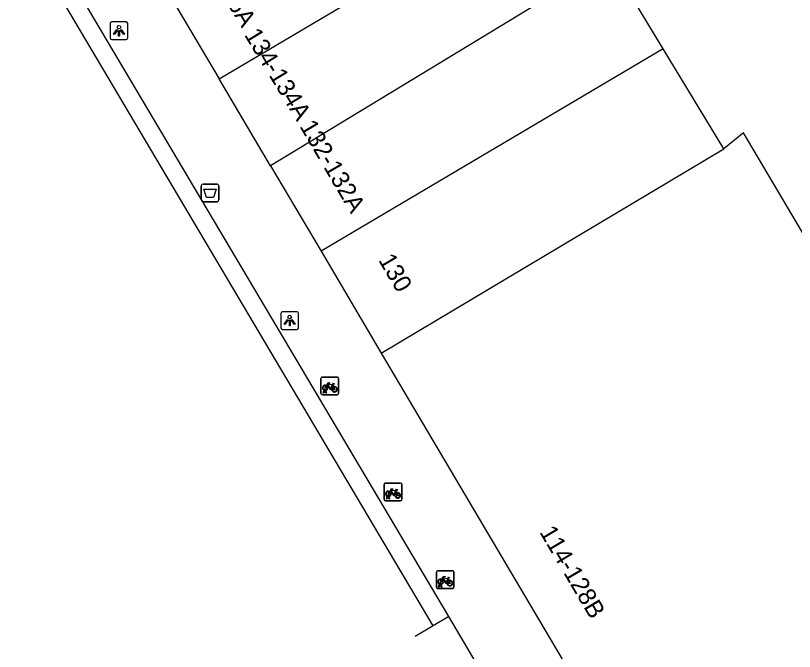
# Model space of a CAD drawing. Extents: x 160861 to 161308, y 384024 to 384878.
# Drawn here: x 161039.26 to 161083.38, y 384444.8 to 384480.81 of the extents above; entities that cross this region are included whole.
import ezdxf

# ---------------------------------------------------------------- set-up
doc = ezdxf.new("R2010")
doc.units = 0
for name, color, linetype in [('IMGEO_Afvalbak', 7, 'Continuous'), ('IMGEO_Fietsenrek', 7, 'Continuous'), ('IMGEO_Fietspad_gesloten', 7, 'Continuous'), ('IMGEO_Fietspad_open', 7, 'Continuous'), ('IMGEO_Lichtpunt', 7, 'Continuous'), ('IMGEO_Pand', 7, 'Continuous'), ('IMGEO_Pand_nummerreeks', 7, 'Continuous')]:
    doc.layers.add(name, color=color, linetype=linetype)

msp = doc.modelspace()

# ---------------------------------------------------------------- linework, layer by layer
at = {"layer": 'IMGEO_Afvalbak'}
for p, q in [((161049.779, 384470.364), (161049.779, 384471.164)), ((161049.779, 384471.164), (161049.779, 384470.364)), ((161049.879, 384471.264), (161050.669, 384471.264)), ((161050.669, 384471.264), (161049.879, 384471.264)), ((161050.769, 384471.164), (161050.769, 384470.364)), ((161050.769, 384470.364), (161050.769, 384471.164)), ((161050.669, 384470.264), (161049.879, 384470.264)), ((161049.879, 384470.264), (161050.669, 384470.264))]:
    msp.add_line(p, q, dxfattribs=at)
msp.add_lwpolyline([(161049.922, 384470.978), (161050.626, 384470.978), (161050.477, 384470.508), (161050.071, 384470.508), (161049.922, 384470.978)], dxfattribs=at)
for centre, start, end in [((161049.879, 384471.164), 90, 180), ((161049.879, 384471.164), 90, 180), ((161050.669, 384471.164), 0, 90), ((161050.669, 384471.164), 360, 90), ((161049.879, 384470.364), 180, 270), ((161049.879, 384470.364), 180, 270), ((161050.669, 384470.364), 270, 0), ((161050.669, 384470.364), 270, 0)]:
    msp.add_arc(centre, 0.1, start, end, dxfattribs=at)
at = {"layer": 'IMGEO_Fietsenrek'}
for p, q in [((161056.556, 384459.416), (161056.556, 384460.257)), ((161056.556, 384460.257), (161056.556, 384459.416)), ((161056.631, 384460.341), (161057.472, 384460.341)), ((161057.472, 384460.341), (161056.631, 384460.341)), ((161057.556, 384460.266), (161057.556, 384459.425)), ((161057.556, 384459.425), (161057.556, 384460.266)), ((161056.683, 384459.425), (161056.722, 384459.585)), ((161056.752, 384459.573), (161056.717, 384459.425)), ((161056.794, 384459.597), (161056.793, 384459.601)), ((161056.835, 384459.425), (161056.801, 384459.567)), ((161056.825, 384459.608), (161056.826, 384459.601)), ((161056.833, 384459.571), (161056.868, 384459.425)), ((161057.243, 384459.89), (161057.279, 384459.795)), ((161057.481, 384459.341), (161056.64, 384459.341)), ((161056.64, 384459.341), (161057.481, 384459.341)), ((161056.717, 384459.425), (161056.683, 384459.425)), ((161056.868, 384459.425), (161056.835, 384459.425)), ((161060.137, 384453.412), (161060.137, 384454.253)), ((161060.137, 384454.253), (161060.137, 384453.412)), ((161060.212, 384454.337), (161061.053, 384454.337)), ((161061.053, 384454.337), (161060.212, 384454.337)), ((161061.137, 384454.262), (161061.137, 384453.421)), ((161061.137, 384453.421), (161061.137, 384454.262)), ((161060.824, 384453.886), (161060.86, 384453.791)), ((161061.062, 384453.337), (161060.221, 384453.337)), ((161060.221, 384453.337), (161061.062, 384453.337)), ((161060.264, 384453.421), (161060.303, 384453.581)), ((161060.298, 384453.421), (161060.264, 384453.421)), ((161060.333, 384453.569), (161060.298, 384453.421)), ((161060.375, 384453.593), (161060.374, 384453.597)), ((161060.416, 384453.421), (161060.382, 384453.563)), ((161060.406, 384453.604), (161060.407, 384453.597)), ((161060.414, 384453.567), (161060.449, 384453.421)), ((161060.449, 384453.421), (161060.416, 384453.421)), ((161063.169, 384449.367), (161064.01, 384449.367)), ((161064.01, 384449.367), (161063.169, 384449.367)), ((161063.094, 384448.442), (161063.094, 384449.283)), ((161063.094, 384449.283), (161063.094, 384448.442)), ((161064.094, 384449.292), (161064.094, 384448.451)), ((161064.094, 384448.451), (161064.094, 384449.292)), ((161063.221, 384448.451), (161063.26, 384448.611)), ((161063.29, 384448.599), (161063.255, 384448.451)), ((161063.332, 384448.623), (161063.331, 384448.627)), ((161063.373, 384448.451), (161063.339, 384448.593)), ((161063.363, 384448.634), (161063.364, 384448.627)), ((161063.371, 384448.597), (161063.406, 384448.451)), ((161063.781, 384448.916), (161063.817, 384448.821)), ((161064.019, 384448.367), (161063.178, 384448.367)), ((161063.178, 384448.367), (161064.019, 384448.367)), ((161063.255, 384448.451), (161063.221, 384448.451)), ((161063.406, 384448.451), (161063.373, 384448.451))]:
    msp.add_line(p, q, dxfattribs=at)
for points in [[(161056.869, 384459.867), (161056.964, 384460.031), (161057.05, 384460.017), (161057.052, 384460.008), (161056.996, 384459.997), (161056.969, 384459.952), (161057.225, 384459.911)], [(161057.225, 384459.911), (161057.25, 384459.96), (161057.244, 384459.964), (161057.221, 384459.968), (161057.209, 384459.975), (161057.208, 384459.978), (161057.21, 384459.983), (161057.305, 384459.968), (161057.307, 384459.958), (161057.297, 384459.945), (161057.285, 384459.939), (161057.271, 384459.945), (161057.243, 384459.89)], [(161056.89, 384459.815), (161056.838, 384459.725), (161056.798, 384459.7), (161056.799, 384459.747), (161056.854, 384459.841)], [(161057.165, 384459.623), (161057.115, 384459.623), (161056.924, 384459.874), (161056.905, 384459.842)], [(161057.212, 384459.886), (161056.955, 384459.927), (161056.938, 384459.898), (161057.105, 384459.678), (161057.212, 384459.886)], [(161057.26, 384459.788), (161057.23, 384459.865), (161057.121, 384459.647), (161057.164, 384459.647)], [(161057.194, 384459.647), (161057.314, 384459.646), (161057.27, 384459.76)], [(161057.29, 384459.767), (161057.345, 384459.622), (161057.195, 384459.622)], [(161060.471, 384453.811), (161060.419, 384453.721), (161060.379, 384453.696), (161060.38, 384453.743), (161060.435, 384453.837)], [(161060.45, 384453.863), (161060.545, 384454.027), (161060.631, 384454.013), (161060.633, 384454.004), (161060.577, 384453.993), (161060.55, 384453.948), (161060.806, 384453.907)], [(161060.746, 384453.619), (161060.696, 384453.619), (161060.505, 384453.87), (161060.486, 384453.838)], [(161060.793, 384453.882), (161060.536, 384453.923), (161060.519, 384453.894), (161060.686, 384453.674), (161060.793, 384453.882)], [(161060.841, 384453.784), (161060.811, 384453.861), (161060.702, 384453.643), (161060.745, 384453.643)], [(161060.806, 384453.907), (161060.831, 384453.956), (161060.825, 384453.96), (161060.802, 384453.964), (161060.79, 384453.971), (161060.789, 384453.974), (161060.791, 384453.979), (161060.886, 384453.964), (161060.888, 384453.954), (161060.878, 384453.941), (161060.866, 384453.935), (161060.852, 384453.941), (161060.824, 384453.886)], [(161060.775, 384453.643), (161060.895, 384453.642), (161060.851, 384453.756)], [(161060.871, 384453.763), (161060.926, 384453.618), (161060.776, 384453.618)], [(161063.407, 384448.893), (161063.502, 384449.057), (161063.588, 384449.043), (161063.59, 384449.034), (161063.534, 384449.023), (161063.507, 384448.978), (161063.763, 384448.937)], [(161063.75, 384448.912), (161063.493, 384448.953), (161063.476, 384448.924), (161063.643, 384448.704), (161063.75, 384448.912)], [(161063.763, 384448.937), (161063.788, 384448.986), (161063.782, 384448.99), (161063.759, 384448.994), (161063.747, 384449.001), (161063.746, 384449.004), (161063.748, 384449.009), (161063.843, 384448.994), (161063.845, 384448.984), (161063.835, 384448.971), (161063.823, 384448.965), (161063.809, 384448.971), (161063.781, 384448.916)], [(161063.428, 384448.841), (161063.376, 384448.751), (161063.336, 384448.726), (161063.337, 384448.773), (161063.392, 384448.867)], [(161063.703, 384448.649), (161063.653, 384448.649), (161063.462, 384448.9), (161063.443, 384448.868)], [(161063.798, 384448.814), (161063.768, 384448.891), (161063.659, 384448.673), (161063.702, 384448.673)], [(161063.732, 384448.673), (161063.852, 384448.672), (161063.808, 384448.786)], [(161063.828, 384448.793), (161063.883, 384448.648), (161063.733, 384448.648)]]:
    msp.add_lwpolyline(points, dxfattribs=at)
for centre, radius, start, end in [((161056.634, 384460.263), 0.0779, 92.4484, 184.2845), ((161056.634, 384460.263), 0.0779, 92.4484, 184.2845), ((161057.478, 384460.263), 0.0779, 2.4484, 94.2845), ((161057.478, 384460.263), 0.0779, 2.4484, 94.2845), ((161056.796, 384459.726), 0.159, 62.6766, 242.1369), ((161056.796, 384459.726), 0.129, 63.3192, 238.903), ((161056.776, 384459.597), 0.0499, 12.8025, 158.6934), ((161056.796, 384459.726), 0.159, 253.9967, 271.7867), ((161056.776, 384459.597), 0.0174, 12.8025, 163.4502), ((161056.796, 384459.726), 0.129, 253.415, 269.0204), ((161056.796, 384459.726), 0.129, 283.6043, 43.4302), ((161056.796, 384459.726), 0.159, 283.5766, 46.6042), ((161057.323, 384459.642), 0.159, 113.3408, 178.3217), ((161057.323, 384459.642), 0.159, 187.0065, 105.7708), ((161057.323, 384459.642), 0.129, 113.923, 177.9556), ((161057.323, 384459.642), 0.129, 188.6715, 104.5883), ((161056.634, 384459.419), 0.0779, 182.4484, 274.2845), ((161056.634, 384459.419), 0.0779, 182.4484, 274.2845), ((161057.478, 384459.419), 0.0779, 272.4484, 4.2845), ((161057.478, 384459.419), 0.0779, 272.4484, 4.2845), ((161060.215, 384454.259), 0.0779, 92.4484, 184.2845), ((161060.215, 384454.259), 0.0779, 92.4484, 184.2845), ((161061.059, 384454.259), 0.0779, 2.4484, 94.2845), ((161061.059, 384454.259), 0.0779, 2.4484, 94.2845), ((161060.377, 384453.722), 0.159, 62.6766, 242.1369), ((161060.377, 384453.722), 0.129, 63.3192, 238.903), ((161060.377, 384453.722), 0.129, 283.6043, 43.4302), ((161060.377, 384453.722), 0.159, 283.5766, 46.6042), ((161060.904, 384453.638), 0.159, 113.3408, 178.3217), ((161060.904, 384453.638), 0.159, 187.0065, 105.7708), ((161060.215, 384453.415), 0.0779, 182.4484, 274.2845), ((161060.215, 384453.415), 0.0779, 182.4484, 274.2845), ((161060.357, 384453.593), 0.0499, 12.8025, 158.6934), ((161060.377, 384453.722), 0.159, 253.9967, 271.7867), ((161060.357, 384453.593), 0.0174, 12.8025, 163.4502), ((161060.377, 384453.722), 0.129, 253.415, 269.0204), ((161060.904, 384453.638), 0.129, 113.923, 177.9556), ((161060.904, 384453.638), 0.129, 188.6715, 104.5883), ((161061.059, 384453.415), 0.0779, 272.4484, 4.2845), ((161061.059, 384453.415), 0.0779, 272.4484, 4.2845), ((161063.172, 384449.289), 0.0779, 92.4484, 184.2845), ((161063.172, 384449.289), 0.0779, 92.4484, 184.2845), ((161064.016, 384449.289), 0.0779, 2.4484, 94.2845), ((161064.016, 384449.289), 0.0779, 2.4484, 94.2845), ((161063.334, 384448.752), 0.159, 62.6766, 242.1369), ((161063.334, 384448.752), 0.129, 63.3192, 238.903), ((161063.314, 384448.623), 0.0499, 12.8025, 158.6934), ((161063.334, 384448.752), 0.159, 253.9967, 271.7867), ((161063.314, 384448.623), 0.0174, 12.8025, 163.4502), ((161063.334, 384448.752), 0.129, 253.415, 269.0204), ((161063.334, 384448.752), 0.129, 283.6043, 43.4302), ((161063.334, 384448.752), 0.159, 283.5766, 46.6042), ((161063.861, 384448.668), 0.159, 113.3408, 178.3217), ((161063.861, 384448.668), 0.159, 187.0065, 105.7708), ((161063.861, 384448.668), 0.129, 113.923, 177.9556), ((161063.861, 384448.668), 0.129, 188.6715, 104.5883), ((161063.172, 384448.445), 0.0779, 182.4484, 274.2845), ((161063.172, 384448.445), 0.0779, 182.4484, 274.2845), ((161064.016, 384448.445), 0.0779, 272.4484, 4.2845), ((161064.016, 384448.445), 0.0779, 272.4484, 4.2845)]:
    msp.add_arc(centre, radius, start, end, dxfattribs=at)
at = {"layer": 'IMGEO_Fietspad_gesloten'}
for points in [[(161062.919, 384446.259), (161039.255, 384486.177)], [(161062.919, 384446.259), (161061.891, 384445.653)]]:
    msp.add_lwpolyline(points, dxfattribs=at)
at = {"layer": 'IMGEO_Fietspad_open'}
for points in [[(161063.799, 384446.778), (161040.086, 384486.747)], [(161063.799, 384446.778), (161062.919, 384446.259)], [(161065.547, 384443.832), (161063.799, 384446.778)]]:
    msp.add_lwpolyline(points, dxfattribs=at)
at = {"layer": 'IMGEO_Lichtpunt'}
for p, q in [((161044.613, 384480.353), (161044.613, 384479.546)), ((161044.613, 384480.353), (161044.613, 384479.546)), ((161045.515, 384480.448), (161044.707, 384480.448)), ((161045.515, 384480.448), (161044.707, 384480.448)), ((161045.609, 384479.546), (161045.609, 384480.353)), ((161045.609, 384479.546), (161045.609, 384480.353)), ((161044.707, 384479.452), (161045.515, 384479.452)), ((161044.707, 384479.452), (161045.515, 384479.452)), ((161054.289, 384463.938), (161054.289, 384463.131)), ((161054.289, 384463.938), (161054.289, 384463.131)), ((161055.191, 384464.033), (161054.383, 384464.033)), ((161055.191, 384464.033), (161054.383, 384464.033)), ((161055.285, 384463.131), (161055.285, 384463.938)), ((161055.285, 384463.131), (161055.285, 384463.938)), ((161054.383, 384463.037), (161055.191, 384463.037)), ((161054.383, 384463.037), (161055.191, 384463.037))]:
    msp.add_line(p, q, dxfattribs=at)
for points in [[(161044.987, 384480.017), (161045.026, 384479.989), (161044.838, 384479.727), (161044.8, 384479.754), (161044.987, 384480.017)], [(161045.089, 384479.969), (161045.136, 384479.969), (161045.136, 384479.647), (161045.089, 384479.647), (161045.089, 384479.969)], [(161045.199, 384479.989), (161045.237, 384480.016), (161045.424, 384479.754), (161045.385, 384479.726), (161045.199, 384479.989)], [(161054.663, 384463.602), (161054.702, 384463.574), (161054.514, 384463.312), (161054.476, 384463.339), (161054.663, 384463.602)], [(161054.765, 384463.554), (161054.812, 384463.554), (161054.812, 384463.232), (161054.765, 384463.232), (161054.765, 384463.554)], [(161054.875, 384463.574), (161054.913, 384463.601), (161055.1, 384463.339), (161055.061, 384463.311), (161054.875, 384463.574)]]:
    msp.add_lwpolyline(points, dxfattribs=at)
for centre in [(161045.112, 384480.151), (161054.788, 384463.736)]:
    msp.add_circle(centre, 0.0994, dxfattribs=at)
for centre, start, end in [((161044.707, 384480.353), 90, 180), ((161044.707, 384480.353), 90, 180), ((161045.515, 384480.353), 0, 90), ((161045.515, 384480.353), 0, 90), ((161044.707, 384479.546), 180, 270), ((161044.707, 384479.546), 180, 270), ((161045.515, 384479.546), 270, 0), ((161045.515, 384479.546), 270, 360), ((161054.383, 384463.938), 90, 180), ((161054.383, 384463.938), 90, 180), ((161055.191, 384463.938), 0, 90), ((161055.191, 384463.938), 0, 90), ((161054.383, 384463.131), 180, 270), ((161054.383, 384463.131), 180, 270), ((161055.191, 384463.131), 270, 0), ((161055.191, 384463.131), 270, 360)]:
    msp.add_arc(centre, 0.0946, start, end, dxfattribs=at)
at = {"layer": 'IMGEO_Pand'}
for points in [[(161050.789, 384477.224), (161073.262, 384490.514)], [(161072.904, 384483.963), (161053.697, 384472.306)], [(161075.954, 384478.925), (161072.904, 384483.963)], [(161047.368, 384483.008), (161050.789, 384477.224)], [(161075.954, 384478.925), (161056.563, 384467.459)], [(161079.386, 384473.255), (161075.954, 384478.925)], [(161053.697, 384472.306), (161050.789, 384477.224)], [(161094.201, 384451.035), (161087.735, 384461.947), (161080.492, 384474.172), (161079.386, 384473.255)], [(161059.97, 384461.697), (161079.386, 384473.255)], [(161053.697, 384472.306), (161056.563, 384467.459)], [(161056.563, 384467.459), (161059.97, 384461.697)], [(161059.97, 384461.697), (161067.054, 384449.718), (161074.052, 384437.883), (161077.552, 384431.965)]]:
    msp.add_lwpolyline(points, dxfattribs=at)

# ---------------------------------------------------------------- texts
at = {"layer": 'IMGEO_Pand_nummerreeks'}
for s, rotation, p in [('136-136A', 301.1088, (161049.084, 384485.034)), ('134-134A', 301.3832, (161052.186, 384479.718)), ('132-132A', 300.4453, (161055.325, 384474.538)), ('130', 300.5976, (161059.783, 384466.965)), ('114-128B', 300.5358, (161068.913, 384451.563))]:
    msp.add_text(s, height=1, rotation=rotation, dxfattribs=at).set_placement(p)

doc.saveas('drawing.dxf')
